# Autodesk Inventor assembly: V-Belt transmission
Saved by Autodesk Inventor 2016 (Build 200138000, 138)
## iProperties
Created: 2015-03
Part Number: V-Belt transmission
Document SubType Name: Assembly
Designer: Uglješa
ClientObjectVersion: 1
Author: Uglješa
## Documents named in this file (4)
- C:\Users\Ugljesa\Desktop\Turbokompr\Assembly1\Design Accelerator\V-Belt transmission2.iam
- C:\Users\Ugljesa\Desktop\Turbokompr\Assembly1\Design Accelerator\V-Belt2.ipt
- C:\Users\Ugljesa\Desktop\Turbokompr\Assembly1\Design Accelerator\Grooved Pulley12.ipt
- C:\Users\Ugljesa\Desktop\Turbokompr\Assembly1\Design Accelerator\Grooved Pulley21.ipt
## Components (8 placed, 3 different names)
1. Grooved Pulley1:1 — Flush:1, Rotation:1
2. Grooved Pulley2:1 — Flush:2, Rotation:1
3. V-Belt:1 — Flush:1, Flush:2
4. V-Belt:2
5. V-Belt:3
6. V-Belt:4
7. V-Belt:5
8. V-Belt:6
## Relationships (3: Flush 2, RelateRotation 1)
- Flush:1: Grooved Pulley1:1 ↔ V-Belt:1
- Flush:2: Grooved Pulley2:1 ↔ V-Belt:1
- Rotation:1 [RelateRotation]: Grooved Pulley1:1 ↔ Grooved Pulley2:1
